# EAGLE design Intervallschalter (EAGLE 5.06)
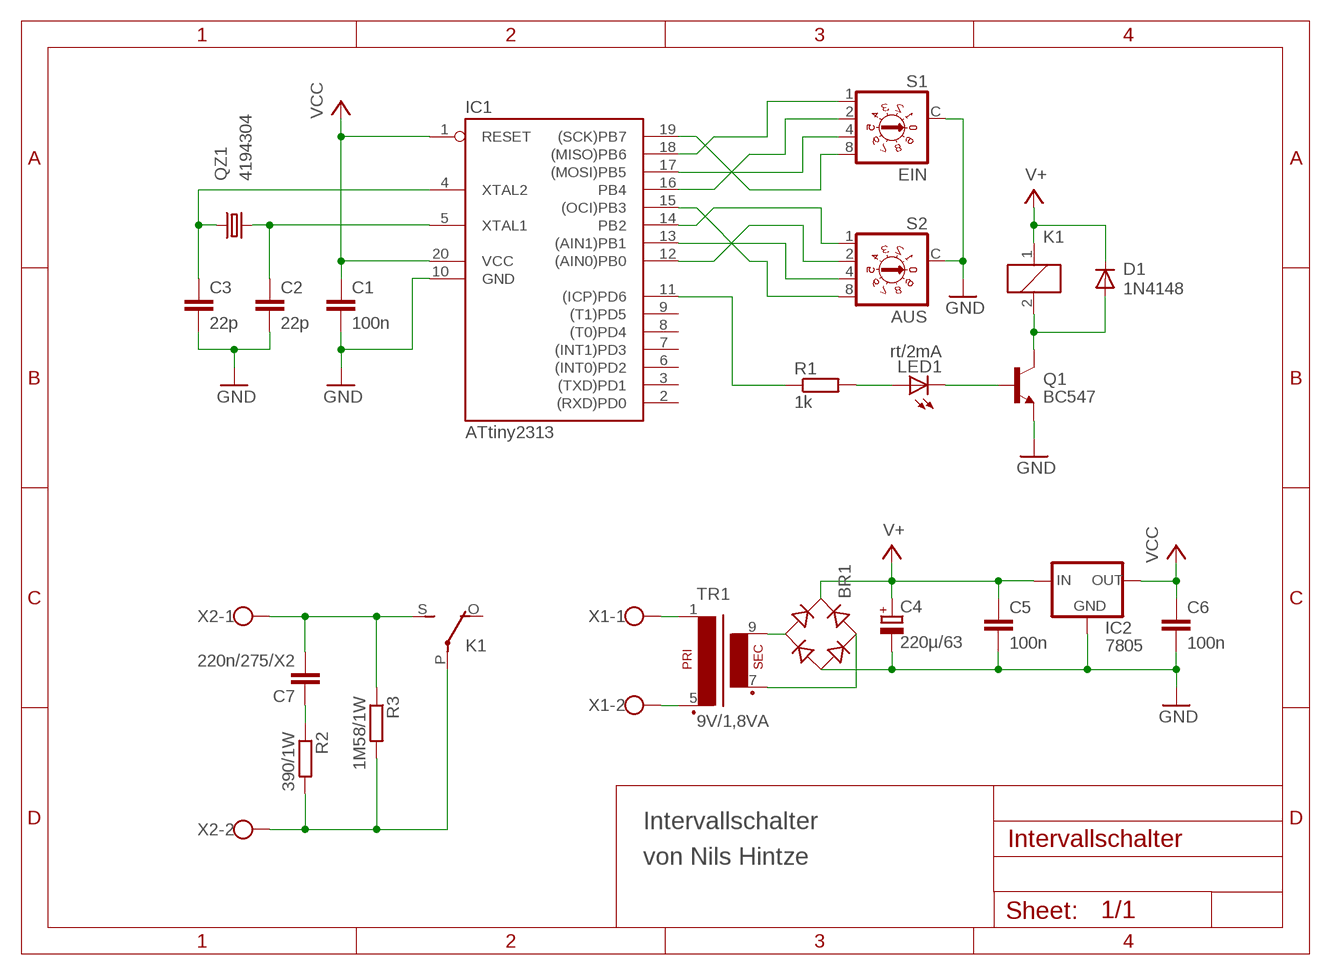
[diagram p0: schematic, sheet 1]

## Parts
BR1  B-DIL  [B-DIL]
C1  100n  C-EU025-024X044  [C025-024X044]
C2  22p  C-EU025-024X044  [C025-024X044]
C3  22p  C-EU025-024X044  [C025-024X044]
C4  220µ/63  CPOL-EUE5-10.5  [E5-10,5]
C5  100n  C-EU025-024X044  [C025-024X044]
C6  100n  C-EU025-024X044  [C025-024X044]
C7  220n/275/X2  C22/8  [C22.5B8]
D1  1N4148  1N4148DO35-7  [DO35-7]
IC1  ATtiny2313  AT90S2313P  [DIL20]
IC2  7805  78XXS  [78XXS]
K1  G5L  [G5LE]
LED1  rt/2mA  LED5MM  [LED5MM]
Q1  BC547  BC548  [TO92-EBC]
QZ1  4194304  HC49S  [HC49S]
R1  1k  R-EU_0207/7  [0207/7]
R2  390/1W  R-EU_0617/5V  [0617V]
R3  1M58/1W  R-EU_0817/7V  [P0817V]
S1  EIN  A1353BCD  [A1353BCD]
S2  AUS  A1353BCD  [A1353BCD]
TR1  9V/1,8VA  EI30-1  [EI30-1]
X1  W237-2N  [W237-2N]
X2  W237-2N  [W237-2N]

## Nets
GND: BR1.- C1.2 C2.2 C3.2 C4.- C5.2 C6.2 IC1.10(GND) IC2.GND Q1.E S1.C S2.C
N$1: IC1.17((MOSI)PB5) S1.4
N$2: IC1.19((SCK)PB7) S1.8
N$3: IC1.15((OCI)PB3) S2.8
N$4: IC1.16(PB4) S1.2
N$5: IC1.18((MISO)PB6) S1.1
N$6: IC1.13((AIN1)PB1) S2.4
N$7: IC1.12((AIN0)PB0) S2.2
N$8: IC1.14(PB2) S2.1
N$9: C2.1 IC1.5(XTAL1) QZ1.2
N$10: C3.1 IC1.4(XTAL2) QZ1.1
N$11: BR1.AC2 TR1.9(S4)
N$12: C7.2 K1.S(2:S) R3.1 X2.1
N$13: K1.P(2:P) R2.2 R3.2 X2.2
N$14: D1.A K1.2 Q1.C
N$15: C7.1 R2.1
N$16: LED1.A R1.2
N$17: LED1.K(C) Q1.B
N$18: IC1.11((ICP)PD6) R1.1
N$19: TR1.5(P2) X1.2
N$20: TR1.1 X1.1
N$21: BR1.AC1 TR1.7(S3)
V+: BR1.+ C4.+ C5.1 D1.C IC2.IN K1.1
VCC: C1.1 C6.1 IC1.1(RESET) IC1.20(VCC) IC2.OUT
Unconnected: IC1.2((RXD)PD0) IC1.3((TXD)PD1) IC1.6((INT0)PD2) IC1.7((INT1)PD3) IC1.8((T0)PD4) IC1.9((T1)PD5) K1.O(2:O)

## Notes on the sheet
- Intervallschalter
- von Nils Hintze

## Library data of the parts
BR1 = nh_rectifier:B-DIL: RECTIFIER
C1-C3 C5 C6 = nh_rcl:C-EU: CAPACITOR, European symbol
C4 = nh_rcl:CPOL-EU: POLARIZED CAPACITOR, European symbol
C7 = capacitor-wima:C: CAPACITOR
D1 = diode:1N4148: DIODE
IC1 = atmel:AT90S2313: MICROCONTROLLER 2 Kbytes FLASH 128 bytes SRAM 128 bytes EEPROM UART
IC2 = v-reg:78XXS: VOLTAGE REGULATOR
K1 = relay:G5L: RELAY 1 x switch, 10 A/120 V AC, 8 A/30 V ADC, Omron
LED1 = nh_led:LED: LED
Q1 = transistor-npn:BC548*: NPN Transistor
QZ1 = nh-quarze:HC49
R1-R3 = nh_rcl:R-EU_: RESISTOR, European symbol
S1 S2 = switch-dil:A1353BCD: DIL/CODE SWITCH
TR1 = trafo:EI30-1: TRANSFORMER 1 primary winding, 1 secondary winding ERA
X1 X2 = con-wago-508:W237-2N: WAGO SREW CLAMP

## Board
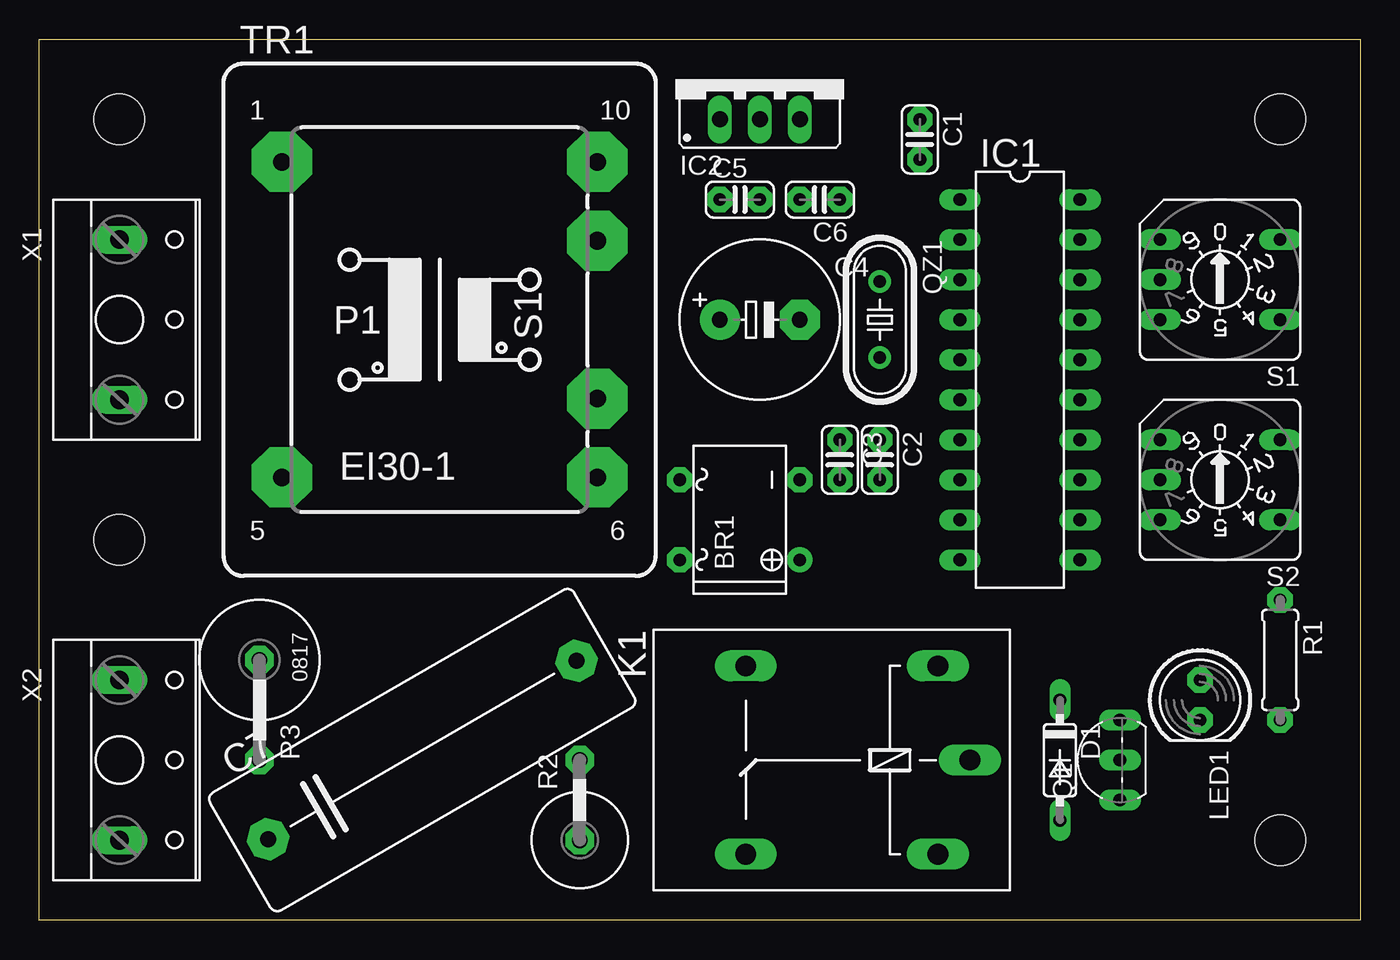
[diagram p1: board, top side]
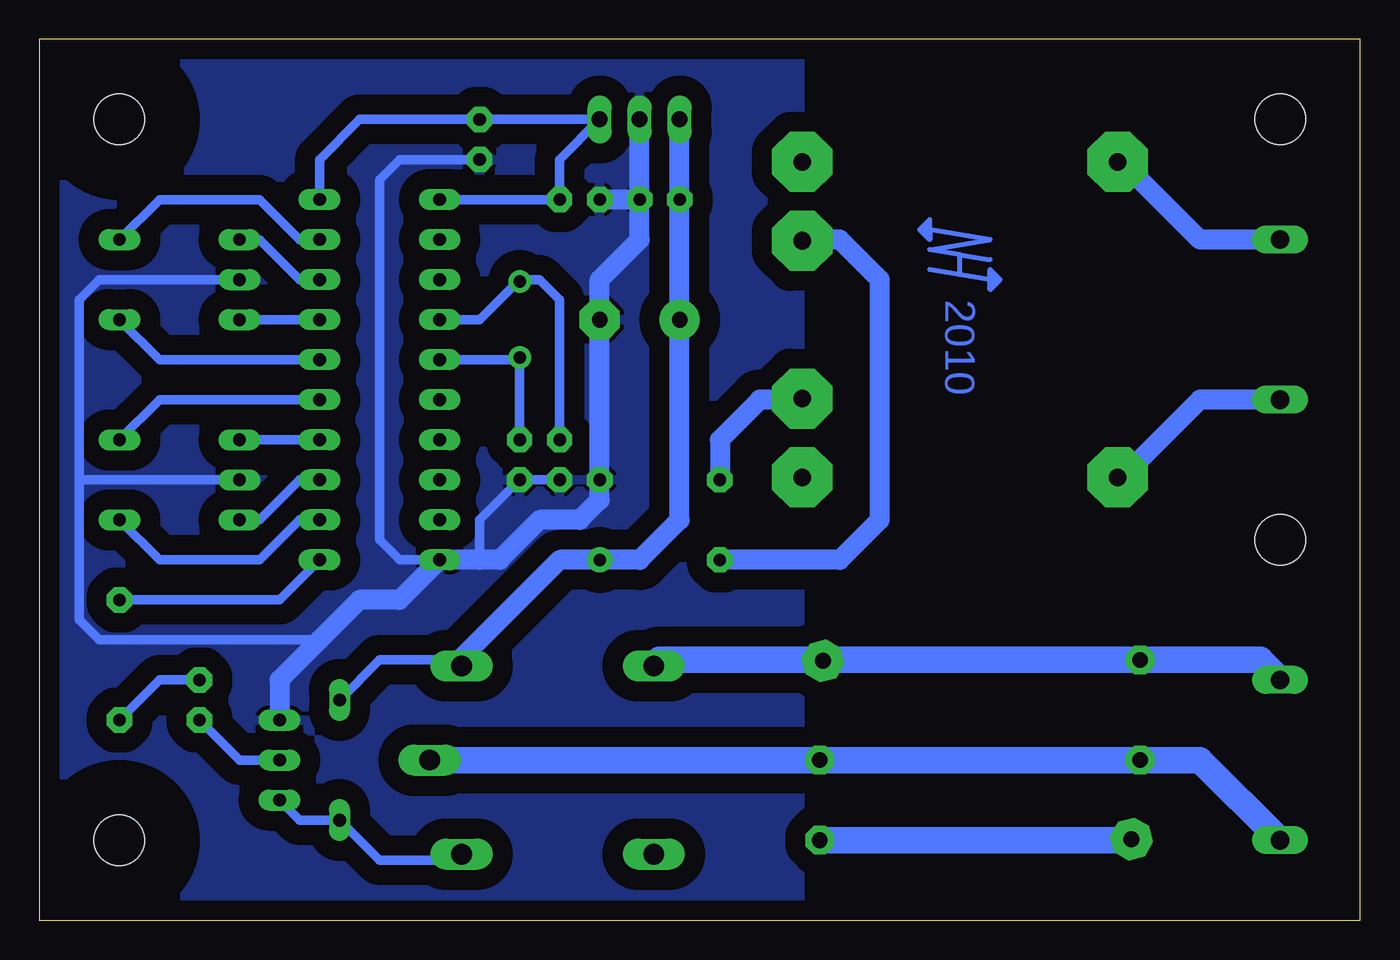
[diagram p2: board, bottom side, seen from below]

Size 83.82 x 55.88 mm. Coordinates in mm from the lower left corner, seen from the top.
Outline: 0,0 0,55.88 83.82,55.88 83.82,0 0,0
Copper layers (1*16): Top 0.035mm / dielectric 1.5mm / Bottom 0.035mm
Design rules "default": minimum track width 10mil, minimum drill 24mil, track to track 8mil, track to pad 8mil, pad to pad 8mil, via to via 8mil, smd to smd 8mil, copper to edge 40mil, drill to drill 8mil, minimum pad ring 10mil, minimum via ring 8mil, stop-mask expansion 4mil, vias tented up to drill 0mil, thermal gap 10mil
Holes 3.2 mm at 5.08,50.8 5.08,24.13 78.74,50.8 78.74,5.08
bRestrict: area 74.9,1.3 to 82.5,8.9; area 74.9,47 to 82.5,54.6; area 1.3,47 to 8.9,54.6; area 1.3,20.3 to 8.9,27.9

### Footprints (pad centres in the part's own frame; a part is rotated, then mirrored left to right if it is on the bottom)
B-DIL = drill 0.8 pad 1.6 round: + -2.54,-3.81 | drill 0.8 pad 1.6 octagon: - 2.54,-3.81; AC1 2.54,3.81; AC2 -2.54,3.81
C025-024X044 = drill 0.8 pad 1.6 octagon: 1 -1.27,0; 2 1.27,0
E5-10,5 = drill 1 pad 2.54 round: + -2.54,0 | drill 1 pad 2.54 octagon: - 2.54,0
C22.5B8 = drill 1.016 pad 2.54 octagon: 1 -11.303,0; 2 11.303,0
DO35-7 = drill 0.813 long: A 3.81,0; C -3.81,0
DIL20 = drill 0.813 long: 1 -11.43,-3.81; 2 -8.89,-3.81; 3 -6.35,-3.81; 4 -3.81,-3.81; 5 -1.27,-3.81; 6 1.27,-3.81; 7 3.81,-3.81; 8 6.35,-3.81; 9 8.89,-3.81; 10 11.43,-3.81; 11 11.43,3.81; 12 8.89,3.81; 13 6.35,3.81; 14 3.81,3.81; 15 1.27,3.81; 16 -1.27,3.81; 17 -3.81,3.81; 18 -6.35,3.81; 19 -8.89,3.81; 20 -11.43,3.81
78XXS = drill 1.016 long: GND 0,-2.54; IN -2.54,-2.54; OUT 2.54,-2.54
G5LE = drill 1.321 long: 1 -7.493,-5.969; 2 -7.493,5.969; O 4.699,5.969; P -9.525,0; S 4.699,-5.969
LED5MM = drill 0.8 pad 1.6 octagon: A -1.27,0; K 1.27,0
TO92-EBC = drill 0.813 long: B 0,-1.27; C -2.54,-1.27; E 2.54,-1.27
HC49S = drill 0.8 pad 1.422 round: 1 -2.413,0; 2 2.413,0
0207/7 = drill 0.8 pad 1.6 octagon: 1 -3.81,0; 2 3.81,0
0617V = drill 1 pad 1.8 octagon: 1 -2.54,0; 2 2.54,0
P0817V = drill 1 pad 1.8 octagon: 1 -5.08,0; 2 1.27,0
A1353BCD = drill 0.813 long: 1 3.81,-2.54; 2 -3.81,2.54; 4 3.81,2.54; 8 -3.81,-2.54; C 3.81,0
EI30-1 = drill 1.118 pad 3.81 octagon: 1 -10.008,10.008; 5 -10.008,-10.008; 6 10.008,-10.008; 7 10.008,-5.004; 9 10.008,5.004; 10 10.008,10.008
W237-2N = drill 1.194 long: 1 -5.08,-0.635; 2 5.08,-0.635

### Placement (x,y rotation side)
BR1  44.45,25.4 90 top
C1  55.88,49.53 270 top
C2  53.34,29.21 270 top
C3  50.8,29.21 270 top
C4  45.72,38.1 0 top
C5  44.45,45.72 0 top
C6  49.53,45.72 180 top
C7  24.3,10.79 30 top
D1  64.77,10.16 270 top
IC1  62.23,34.29 270 top
IC2  45.72,53.34 0 top
K1  49.53,10.16 180 top
LED1  73.66,13.97 270 top
Q1  67.31,10.16 90 top
QZ1  53.34,38.1 270 top
R1  78.74,16.51 270 top
R2  34.29,7.62 90 top
R3  13.97,11.43 270 top
S1  74.93,40.64 180 top
S2  74.93,27.94 180 top
TR1  25.4,38.1 0 top
X1  5.71,38.1 270 top
X2  5.71,10.16 270 top

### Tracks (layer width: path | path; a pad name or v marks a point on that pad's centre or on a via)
GND
  Bottom 0.61: 81.28,27.94 S2.C | 81.28,27.94 81.28,39.37 80.01,40.64 S1.C | 81.28,27.94 81.28,19.05 80.01,17.78 66.04,17.78 | C3.2 C2.2 55.88,25.4 55.88,22.86 | IC1.10 60.96,22.86 62.23,24.13 62.23,46.99 60.96,48.26 C1.2
  Bottom 1.27: Q1.E 68.58,15.24 66.04,17.78 63.5,20.32 60.96,20.32 IC1.10 55.88,22.86 54.61,22.86 52.07,25.4 49.53,25.4 48.26,26.67 BR1.- C4.- 48.26,40.64 45.72,43.18 C5.2 | C5.2 IC2.GND | C5.2 C6.2
  pour Bottom (isolate 1.27): 35.56,0 35.56,55.88 83.82,55.88 83.82,0
N$1
  Bottom 0.61: IC1.17 S1.4
N$2
  Bottom 0.61: IC1.19 67.31,43.18 69.85,45.72 76.2,45.72 S1.8
N$3
  Bottom 0.61: S2.8 76.2,33.02 IC1.15
N$4
  Bottom 0.61: IC1.16 76.2,35.56 S1.2
N$5
  Bottom 0.61: IC1.18 67.31,40.64 69.85,43.18 S1.1
N$6
  Bottom 0.61: IC1.13 67.31,27.94 69.85,25.4 S2.4
N$7
  Bottom 0.61: IC1.12 67.31,25.4 69.85,22.86 76.2,22.86 S2.2
N$8
  Bottom 0.61: IC1.14 S2.1
N$9
  Bottom 0.61: 53.34,35.56 QZ1.2 | 53.34,35.56 IC1.5 | C2.1 53.34,35.56
N$10
  Bottom 0.61: 53.34,40.64 QZ1.1 | 53.34,40.64 55.88,38.1 IC1.4 | C3.1 50.8,39.37 52.07,40.64 53.34,40.64
N$11
  Bottom 1.27: BR1.AC2 33.02,22.86 30.48,25.4 30.48,40.64 33.02,43.18 35.56,43.18 35.48,43.1 TR1.9
N$12
  Bottom 1.676: K1.S 44.45,16.13 44.45,16.51 34.29,16.51 | 34.29,16.51 R3.1 6.35,16.51 X2.1 | C7.2 34.23,16.45 34.29,16.51
N$13
  Bottom 1.676: K1.P R2.2 R3.2 10.16,10.16 X2.2
N$14
  Bottom 0.61: K1.2 57.02,3.94 57.15,3.81 62.23,3.81 D1.A 67.31,6.35 Q1.C
N$15
  Bottom 1.676: C7.1 15.18,5.14 15.24,5.08 R2.1
N$16
  Bottom 0.61: R1.2 76.2,15.24 LED1.A
N$17
  Bottom 0.61: Q1.B 71.12,10.16 LED1.K
N$18
  Bottom 0.61: IC1.11 68.58,20.32 R1.1
N$19
  Bottom 1.27: TR1.5 15.24,27.94 10.16,33.02 X1.2
N$20
  Bottom 1.27: TR1.1 15.24,48.26 10.16,43.18 X1.1
N$21
  Bottom 1.27: TR1.7 35.48,33.1 35.56,33.02 38.1,33.02 40.64,30.48 BR1.AC1
N$22
  Bottom 0.305: 27.3,43.81 23.5,43.18 27.3,42.55 25.4,42.23 | 25.4,42.23 23.5,41.91 | 25.4,40.96 25.4,42.23 | 23.5,40.64 25.4,40.96 | 25.4,40.96 27.3,41.27 | 27.3,43.81 27.3,44.45 | 27.3,44.45 27.94,43.81 | 27.3,43.18 27.94,43.81 | 27.3,43.81 27.3,43.18 | 23.5,40.64 23.5,41.27 | 22.86,40.64 23.5,41.27 | 23.5,40.01 22.86,40.64 | 23.5,40.01 23.5,40.64 | 23.5,40.64 23.18,40.64 | 22.86,40.64 23.18,40.64 | 27.3,43.81 27.62,43.81 | 27.62,43.81 27.94,43.81 | 23.5,40.01 23.18,40.64 | 23.18,40.64 23.5,41.27 | 27.3,43.18 27.62,43.81 | 27.3,44.45 27.62,43.81
V+
  Bottom 0.61: D1.C 62.23,16.51 57.15,16.51
  Bottom 1.27: K1.1 57.02,16.38 57.15,16.51 50.8,22.86 BR1.+ 45.72,22.86 43.18,25.4 C4.+ C5.1 IC2.IN
VCC
  Bottom 0.61: IC1.20 66.04,48.26 63.5,50.8 C1.1 IC2.OUT 50.8,48.26 C6.1 IC1.1

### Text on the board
Bottom: 2010
tDocu: EIN | AUS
